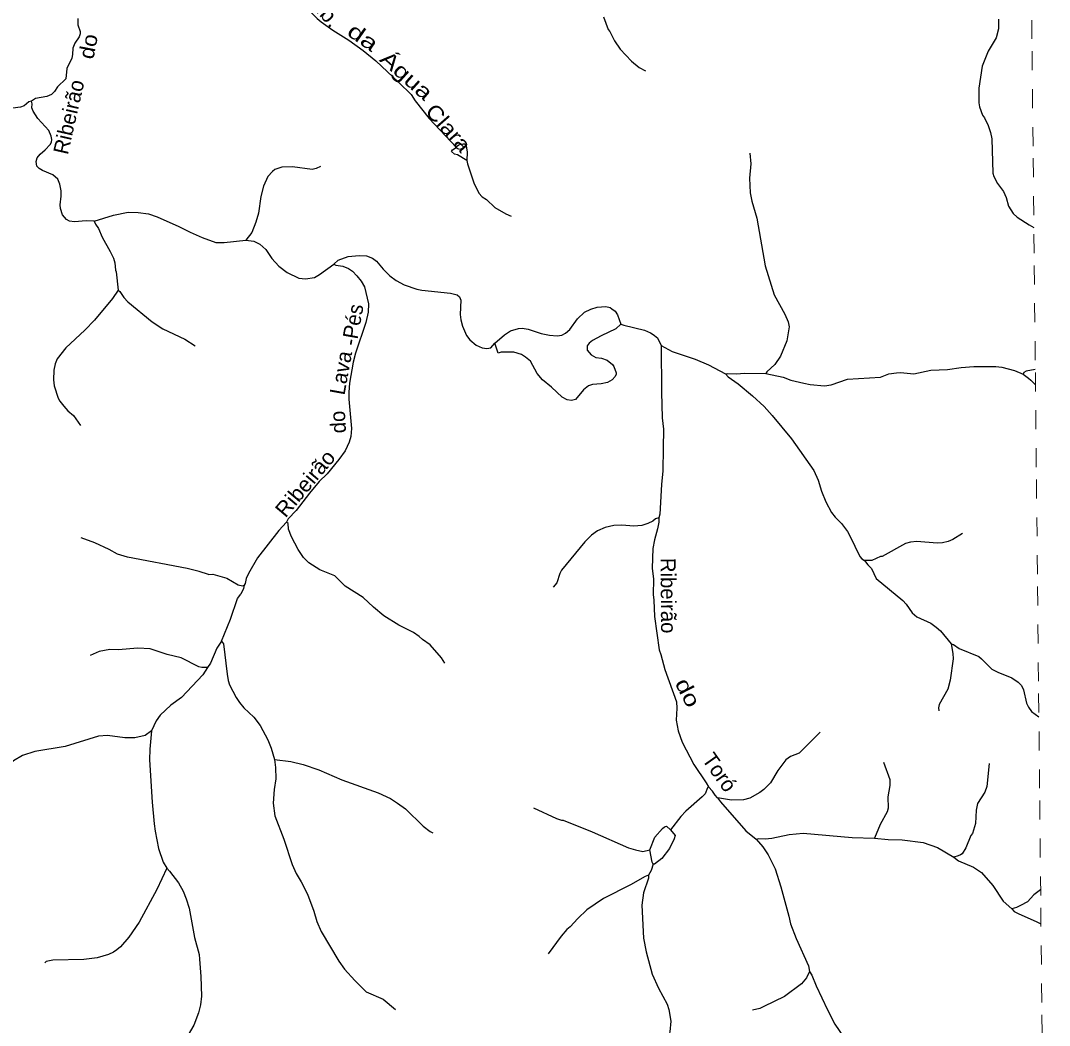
# Model space of a CAD drawing. Extents: x 320.3 to 346.3, y 7455.4 to 7483.3.
# Drawn here: x 340.83 to 346.26, y 7459.49 to 7464.8 of the extents above; entities that cross this region are included whole.
import ezdxf
from ezdxf.enums import TextEntityAlignment as Align

# ---------------------------------------------------------------- set-up
doc = ezdxf.new("R2010")
doc.units = 0
doc.header["$LTSCALE"] = 0.032
doc.linetypes.add('SHORT_DASHED', pattern=[2.7, 1.5, -1.2])
for name, color, linetype, lineweight in [('2', 7, 'Continuous', 25), ('53', 7, 'SHORT_DASHED', 13), ('7', 7, 'Continuous', 25)]:
    doc.layers.add(name, color=color, linetype=linetype, lineweight=lineweight)
doc.layers.add('61', color=7, linetype='Continuous')

msp = doc.modelspace()

# ---------------------------------------------------------------- linework, layer by layer
at = {"layer": '2'}
for points in [[(343.1018, 7464.1059), (343.1072, 7464.1137), (343.115, 7464.1191), (343.1228, 7464.125), (343.1261, 7464.1287), (343.1338, 7464.1355), (343.1411, 7464.1404), (343.1499, 7464.1439), (343.163, 7464.1468), (343.1723, 7464.1458), (343.1788, 7464.1352), (343.1846, 7464.1014), (343.1832, 7464.0579), (343.1329, 7464.0874), (343.1172, 7464.0923)], [(343.3306, 7463.0936), (343.3816, 7463.1375), (343.4129, 7463.1587), (343.4549, 7463.1712), (343.474, 7463.1733), (343.5071, 7463.1684), (343.5753, 7463.146), (343.6189, 7463.1359), (343.6591, 7463.1327), (343.6842, 7463.1369), (343.7044, 7463.1463), (343.7271, 7463.1666), (343.7679, 7463.2226), (343.8048, 7463.2585), (343.8381, 7463.2742), (343.8703, 7463.2839), (343.9173, 7463.2878), (343.9394, 7463.282), (343.9492, 7463.2757), (343.9651, 7463.2628), (343.9789, 7463.2429), (343.9963, 7463.1947), (343.9695, 7463.1691), (343.8912, 7463.1334), (343.8455, 7463.1077), (343.8284, 7463.094), (343.8179, 7463.0798), (343.8183, 7463.0567), (343.84, 7463.0322), (343.8643, 7463.0189), (343.8944, 7463.0141), (343.9241, 7463.0044), (343.9517, 7462.9817), (343.9589, 7462.9704), (343.9709, 7462.9383), (343.9713, 7462.9308), (343.9663, 7462.9183), (343.9506, 7462.9008), (343.9249, 7462.8872), (343.8927, 7462.8792), (343.8457, 7462.8752), (343.8254, 7462.8685), (343.7986, 7462.8483), (343.756, 7462.7972), (343.7349, 7462.7907), (343.7123, 7462.7949), (343.6868, 7462.8098), (343.6297, 7462.8623), (343.5825, 7462.9), (343.5539, 7462.9347), (343.5192, 7462.999), (343.4927, 7463.021), (343.471, 7463.0341), (343.4302, 7463.0463), (343.3638, 7463.0464), (343.3488, 7463.0422)], [(344.1497, 7460.4212), (344.1762, 7460.4867), (344.2159, 7460.5321), (344.226, 7460.5412), (344.2378, 7460.5449), (344.2574, 7460.526), (344.2824, 7460.4953), (344.2775, 7460.4781), (344.2536, 7460.4282), (344.2117, 7460.3739), (344.174, 7460.3443), (344.1671, 7460.3439), (344.1618, 7460.3553)]]:
    msp.add_lwpolyline(points, close=True, dxfattribs=at)
at = {"layer": '53'}
msp.add_lwpolyline([(346.259, 7455.6605), (346.2532, 7456.2254), (346.2474, 7456.7903), (346.2417, 7457.3553), (346.2359, 7457.9202), (346.2301, 7458.4852), (346.2243, 7459.0501), (346.2186, 7459.615), (346.2128, 7460.18), (346.207, 7460.7449), (346.2013, 7461.3098), (346.1955, 7461.8748), (346.1897, 7462.4397), (346.184, 7463.0046), (346.1782, 7463.5696), (346.1724, 7464.1345), (346.1667, 7464.6995), (346.1609, 7465.2644)], dxfattribs=at)
at = {"layer": '7'}
for points in [[(342.1435, 7465.3088), (342.1655, 7465.2439), (342.1816, 7465.1795), (342.1996, 7465.0843), (342.2112, 7465.0534), (342.3071, 7464.9054), (342.3489, 7464.8523), (342.3917, 7464.808), (342.4129, 7464.7906), (342.4746, 7464.7463), (342.56, 7464.693), (342.6361, 7464.6384), (342.7028, 7464.5832), (342.8244, 7464.47), (342.8888, 7464.4068), (342.9106, 7464.3735), (342.9844, 7464.2804), (343.1261, 7464.1287)], [(343.9046, 7464.8166), (343.929, 7464.7496), (343.9377, 7464.7391), (343.9622, 7464.6895), (343.9925, 7464.6457), (344.0519, 7464.5829), (344.093, 7464.5485), (344.1253, 7464.5318)], [(341.1286, 7464.8071), (341.1293, 7464.7745), (341.1402, 7464.7397), (341.1412, 7464.727), (341.1349, 7464.7106), (341.113, 7464.6779), (341.1015, 7464.6516), (341.1007, 7464.6173), (341.0961, 7464.5974), (341.0704, 7464.5437), (341.0658, 7464.4896), (341.022, 7464.4461), (341.0054, 7464.4217), (340.9892, 7464.4062), (340.9655, 7464.3955), (340.9047, 7464.385), (340.8846, 7464.3706)], [(345.99, 7464.8036), (345.9895, 7464.753), (345.9778, 7464.7061), (345.9359, 7464.6356), (345.9043, 7464.5559), (345.8857, 7464.44), (345.8864, 7464.3623), (345.8897, 7464.3417), (345.9051, 7464.2977), (345.917, 7464.2837), (345.9356, 7464.2431), (345.9481, 7464.2064), (345.9547, 7464.1732), (345.9595, 7463.9918), (345.965, 7463.974), (345.9847, 7463.9362), (346.0169, 7463.8939), (346.0301, 7463.8629), (346.0427, 7463.8177), (346.0682, 7463.7786), (346.0881, 7463.7583), (346.1518, 7463.7191), (346.1769, 7463.7037)], [(340.8846, 7464.3706), (340.87, 7464.3672), (340.8444, 7464.3473), (340.8255, 7464.3396), (340.7181, 7464.3255), (340.6758, 7464.3131), (340.6066, 7464.2651), (340.5819, 7464.2527), (340.4992, 7464.2423), (340.4007, 7464.2156), (340.3083, 7464.1825), (340.2685, 7464.1635)], [(341.2155, 7463.7378), (341.1718, 7463.7391), (341.1112, 7463.7337), (341.0842, 7463.7385), (341.069, 7463.7464), (341.0485, 7463.771), (341.0363, 7463.805), (341.0351, 7463.8243), (341.0414, 7463.8698), (341.0414, 7463.8986), (341.0337, 7463.9333), (341.0227, 7463.9595), (340.9974, 7463.983), (340.9425, 7464.0048), (340.925, 7464.0152), (340.9125, 7464.0281), (340.9081, 7464.0529), (340.9142, 7464.0716), (340.9303, 7464.0915), (340.9563, 7464.1138), (340.9825, 7464.1431), (340.9896, 7464.1552), (340.9907, 7464.1694), (340.9883, 7464.1862), (340.975, 7464.2163), (340.9168, 7464.2796), (340.8922, 7464.319), (340.8857, 7464.3359), (340.8873, 7464.3573), (340.8846, 7464.3706)], [(343.1832, 7464.0579), (343.1864, 7464.0403), (343.2204, 7463.9397), (343.2461, 7463.8853), (343.2634, 7463.8667), (343.2867, 7463.8518), (343.3298, 7463.8105), (343.3884, 7463.7766), (343.4173, 7463.7651)], [(344.6764, 7464.0966), (344.6824, 7464.0399), (344.6757, 7463.9644), (344.6781, 7463.888), (344.6873, 7463.8436), (344.7145, 7463.7535), (344.7583, 7463.503), (344.8051, 7463.3494), (344.8623, 7463.2475), (344.8794, 7463.2074), (344.8839, 7463.1804), (344.8732, 7463.1064), (344.8395, 7463.0257), (344.809, 7462.9809), (344.7669, 7462.9423), (344.7614, 7462.934)], [(342.4101, 7464.0258), (342.3871, 7464.0151), (342.3667, 7464.0105), (342.2628, 7464.0241), (342.2057, 7464.0237), (342.169, 7464.0106), (342.1558, 7464.0007), (342.1326, 7463.9736), (342.1096, 7463.922), (342.0944, 7463.8682), (342.0823, 7463.7798), (342.0692, 7463.7325), (342.0468, 7463.6786), (342.0149, 7463.6376)], [(341.2155, 7463.7378), (341.3167, 7463.7701), (341.3951, 7463.7847), (341.4476, 7463.7841), (341.5017, 7463.7766), (341.5467, 7463.7616), (341.6626, 7463.7104), (341.7221, 7463.6792), (341.7854, 7463.6517), (341.8572, 7463.6256), (341.9019, 7463.6245), (342.0149, 7463.6376)], [(341.2155, 7463.7378), (341.2226, 7463.7217), (341.2376, 7463.7001), (341.2566, 7463.6541), (341.3, 7463.5785), (341.3169, 7463.543), (341.3234, 7463.5187), (341.3271, 7463.4788), (341.3309, 7463.47), (341.3418, 7463.3741)], [(342.0149, 7463.6376), (342.0574, 7463.6321), (342.0897, 7463.6159), (342.1208, 7463.5877), (342.1526, 7463.5416), (342.1905, 7463.5008), (342.2343, 7463.4666), (342.2959, 7463.4378), (342.3306, 7463.4336), (342.3789, 7463.4407), (342.4048, 7463.456), (342.4806, 7463.5112)], [(342.4806, 7463.5112), (342.5027, 7463.5318), (342.5564, 7463.5512), (342.6139, 7463.5573), (342.6522, 7463.5558), (342.6845, 7463.5432), (342.7065, 7463.527), (342.7414, 7463.4851), (342.7767, 7463.4488), (342.8099, 7463.4244), (342.8526, 7463.4019), (342.9193, 7463.3785), (342.9447, 7463.3732), (343.0971, 7463.3586), (343.1314, 7463.3492), (343.1446, 7463.3385), (343.151, 7463.3204), (343.1479, 7463.2462), (343.1512, 7463.2173), (343.1592, 7463.184), (343.1811, 7463.134), (343.1991, 7463.1114), (343.2319, 7463.0844), (343.2634, 7463.0698), (343.2877, 7463.0656), (343.3092, 7463.0688), (343.3306, 7463.0936)], [(342.4806, 7463.5112), (342.4905, 7463.5066), (342.5274, 7463.5007), (342.558, 7463.4878), (342.5788, 7463.4734), (342.6018, 7463.4502), (342.6247, 7463.4216), (342.6419, 7463.3908), (342.6643, 7463.3012), (342.6615, 7463.2581), (342.6502, 7463.2031), (342.5955, 7463.042), (342.5826, 7462.9945), (342.5624, 7462.8831), (342.5589, 7462.8364), (342.56, 7462.7979), (342.574, 7462.6445), (342.5693, 7462.6008), (342.5615, 7462.5709), (342.5396, 7462.5254), (342.5065, 7462.4795), (342.4447, 7462.4048), (342.4037, 7462.3633), (342.3514, 7462.3026), (342.2817, 7462.2117), (342.2397, 7462.1679), (342.2302, 7462.15)], [(341.3418, 7463.3741), (341.3112, 7463.33), (341.2167, 7463.2159), (341.1649, 7463.1626), (341.0648, 7463.0701), (341.0198, 7463.0107), (341.0088, 7462.985), (341.001, 7462.952), (340.9994, 7462.9), (341.0036, 7462.8691), (341.0252, 7462.8033), (341.0336, 7462.7874), (341.055, 7462.7616), (341.0751, 7462.7365), (341.1056, 7462.7116), (341.1421, 7462.6597)], [(341.3418, 7463.3741), (341.3495, 7463.3676), (341.3709, 7463.3352), (341.3925, 7463.3119), (341.5205, 7463.2068), (341.5776, 7463.1705), (341.6931, 7463.1158), (341.7488, 7463.0796)], [(343.9963, 7463.1947), (344.0119, 7463.1883), (344.1217, 7463.1619), (344.1529, 7463.1489), (344.1672, 7463.1407), (344.1886, 7463.1215), (344.2093, 7463.0814)], [(344.2093, 7463.0814), (344.2098, 7462.8362), (344.2147, 7462.6998), (344.2206, 7462.641), (344.2194, 7462.5396), (344.2169, 7462.4202), (344.2098, 7462.349), (344.2014, 7462.1914), (344.1964, 7462.1715)], [(344.2093, 7463.0814), (344.2666, 7463.0496), (344.3878, 7463.0093), (344.4591, 7462.9792), (344.5484, 7462.9319)], [(344.7614, 7462.934), (344.8523, 7462.9141), (344.8927, 7462.8996), (344.9622, 7462.883), (344.996, 7462.8767), (345.0718, 7462.8696), (345.106, 7462.8749), (345.1923, 7462.9047), (345.367, 7462.9154), (345.4118, 7462.9322), (345.4514, 7462.9383), (345.4718, 7462.9391), (345.543, 7462.9323), (345.6322, 7462.9521), (345.72, 7462.9547), (345.793, 7462.9662), (345.8606, 7462.971), (345.9769, 7462.9702), (346.0071, 7462.9667), (346.0752, 7462.9499), (346.1195, 7462.9301)], [(344.5484, 7462.9319), (344.559, 7462.9339), (344.608, 7462.9319), (344.6475, 7462.9355), (344.7614, 7462.934)], [(344.5484, 7462.9319), (344.5629, 7462.9163), (344.6146, 7462.8799), (344.691, 7462.8166), (344.7524, 7462.7594), (344.7955, 7462.7116), (344.8967, 7462.589), (345.015, 7462.422), (345.0378, 7462.3707), (345.0554, 7462.3136), (345.0779, 7462.2575), (345.109, 7462.1997), (345.1272, 7462.1754), (345.1605, 7462.1416), (345.1919, 7462.0997), (345.2051, 7462.0779), (345.2576, 7461.9676), (345.2678, 7461.9558), (345.282, 7461.9477)], [(346.1845, 7462.9557), (346.1367, 7462.9459), (346.1245, 7462.9386), (346.1195, 7462.9301)], [(346.1195, 7462.9301), (346.1491, 7462.9087), (346.1603, 7462.898), (346.1854, 7462.8741)], [(344.1964, 7462.1715), (344.1793, 7462.1667), (344.1641, 7462.1549), (344.1392, 7462.1418), (344.1071, 7462.1325), (344.0653, 7462.1281), (344.0005, 7462.1343), (343.9597, 7462.1325), (343.9126, 7462.1221), (343.8725, 7462.104), (343.8409, 7462.0802), (343.8066, 7462.0462), (343.682, 7461.896), (343.6729, 7461.8787), (343.6581, 7461.8292), (343.6378, 7461.8061)], [(344.1964, 7462.1715), (344.1962, 7462.1497), (344.1896, 7462.1136), (344.1729, 7462.0568), (344.1647, 7462.0103), (344.1616, 7461.9061), (344.1678, 7461.8485), (344.1663, 7461.7677), (344.1707, 7461.7375), (344.1744, 7461.6509), (344.1986, 7461.476), (344.2076, 7461.4515), (344.2279, 7461.3717), (344.2902, 7461.2005), (344.2917, 7461.1688), (344.2878, 7461.1048), (344.2981, 7461.049), (344.3189, 7460.9883), (344.3811, 7460.8709), (344.4473, 7460.7736), (344.4584, 7460.753)], [(342.2302, 7462.15), (342.1897, 7462.1054), (342.0778, 7461.9606), (342.029, 7461.8789), (342.0175, 7461.8527), (342.013, 7461.8267), (342.0076, 7461.8166)], [(343.0666, 7461.4062), (343.0485, 7461.4343), (342.9898, 7461.5017), (342.9484, 7461.5303), (342.9303, 7461.5468), (342.9014, 7461.5672), (342.8237, 7461.6058), (342.7437, 7461.6544), (342.689, 7461.7003), (342.6359, 7461.7511), (342.5399, 7461.8122), (342.4864, 7461.8658), (342.4069, 7461.8972), (342.3476, 7461.9349), (342.3201, 7461.9624), (342.2924, 7462.0057), (342.2561, 7462.0729), (342.2416, 7462.1118), (342.2384, 7462.1426), (342.2302, 7462.15)], [(341.8182, 7461.8733), (341.7695, 7461.8897), (341.7067, 7461.9048), (341.3913, 7461.9643), (341.3389, 7461.9798), (341.2948, 7462.0048), (341.2192, 7462.0412), (341.147, 7462.0667)], [(345.8003, 7462.0893), (345.7496, 7462.0587), (345.724, 7462.0476), (345.6952, 7462.0408), (345.6663, 7462.0394), (345.5597, 7462.0474), (345.526, 7462.0442), (345.4996, 7462.0375), (345.3763, 7461.9689), (345.3666, 7461.9677), (345.3208, 7461.9475), (345.282, 7461.9477)], [(345.282, 7461.9477), (345.2997, 7461.9238), (345.3196, 7461.9051), (345.3445, 7461.8515), (345.4848, 7461.7361), (345.5025, 7461.7171), (345.535, 7461.6713), (345.5594, 7461.6501), (345.6321, 7461.6168), (345.6615, 7461.5961), (345.683, 7461.5753), (345.7408, 7461.5076)], [(341.8182, 7461.8733), (341.8407, 7461.8752), (341.9147, 7461.8543), (341.9752, 7461.819), (341.9979, 7461.8142), (342.0076, 7461.8166)], [(342.0076, 7461.8166), (342.0035, 7461.8003), (341.9888, 7461.7691)], [(341.8879, 7461.5223), (341.9356, 7461.6371), (341.9724, 7461.7475), (341.9888, 7461.7691)], [(341.8879, 7461.5223), (341.863, 7461.484), (341.829, 7461.4052), (341.8138, 7461.3821)], [(341.8879, 7461.5223), (341.8984, 7461.5081), (341.9168, 7461.3482), (341.9226, 7461.3136), (341.9299, 7461.2913), (341.9638, 7461.2244), (341.9816, 7461.1981), (342.0054, 7461.1705), (342.0576, 7461.1198), (342.0912, 7461.0765), (342.1327, 7461.0009), (342.1494, 7460.9572), (342.1673, 7460.8969)], [(345.7408, 7461.5076), (345.7498, 7461.456), (345.7512, 7461.4276), (345.7346, 7461.316), (345.7219, 7461.2682), (345.677, 7461.1865), (345.6735, 7461.17), (345.6756, 7461.1544)], [(345.7408, 7461.5076), (345.7525, 7461.5034), (345.7822, 7461.4823), (345.8854, 7461.4398), (345.9005, 7461.4287), (345.955, 7461.3742), (345.9873, 7461.3578), (346.0602, 7461.3283), (346.0932, 7461.3048), (346.1116, 7461.2871), (346.1226, 7461.264), (346.1375, 7461.1951), (346.1486, 7461.1728), (346.1643, 7461.1504), (346.2032, 7461.123)], [(341.8138, 7461.3821), (341.7842, 7461.3826), (341.7682, 7461.3866), (341.6748, 7461.433), (341.6009, 7461.4518), (341.5104, 7461.4814), (341.4448, 7461.484), (341.3419, 7461.476), (341.2967, 7461.4771), (341.2421, 7461.4662), (341.1936, 7461.4465)], [(341.8138, 7461.3821), (341.7888, 7461.3433), (341.6762, 7461.2241), (341.6205, 7461.1833), (341.5628, 7461.1305), (341.5419, 7461.1005), (341.5179, 7461.048)], [(341.5179, 7461.048), (341.4833, 7461.024), (341.4297, 7461.0119), (341.3766, 7461.0117), (341.2852, 7461.0238), (341.2372, 7461.0209), (341.0621, 7460.9662), (340.9007, 7460.9393), (340.8364, 7460.9173), (340.7884, 7460.8897), (340.7424, 7460.8496), (340.6198, 7460.6949), (340.5795, 7460.6486), (340.5584, 7460.6174)], [(341.5179, 7461.048), (341.5079, 7460.9518), (341.5074, 7460.8956), (341.5205, 7460.6724), (341.531, 7460.5584), (341.5361, 7460.5189), (341.555, 7460.4273), (341.5793, 7460.3555), (341.5979, 7460.3229)], [(345.0489, 7461.041), (344.9368, 7460.931), (344.8914, 7460.9123), (344.8673, 7460.8951), (344.8253, 7460.8382), (344.7855, 7460.7745), (344.7508, 7460.7383), (344.7294, 7460.7226), (344.6776, 7460.6933), (344.643, 7460.6834), (344.581, 7460.6825), (344.507, 7460.6956)], [(342.1673, 7460.8969), (342.1726, 7460.8545), (342.1742, 7460.7952), (342.1648, 7460.7392), (342.16, 7460.6672), (342.1689, 7460.6004), (342.2164, 7460.4773), (342.2596, 7460.3432), (342.2817, 7460.2946), (342.3083, 7460.251), (342.3408, 7460.186), (342.3752, 7460.0973), (342.3911, 7460.0425), (342.4128, 7459.9897), (342.5062, 7459.8327), (342.5367, 7459.7912), (342.5913, 7459.7308), (342.6517, 7459.6708), (342.7411, 7459.6328), (342.8059, 7459.5783)], [(342.1673, 7460.8969), (342.2525, 7460.8858), (342.3181, 7460.871), (342.4006, 7460.842), (342.5231, 7460.7905), (342.7143, 7460.721), (342.7801, 7460.6904), (342.8169, 7460.6668), (342.8581, 7460.6359), (342.9514, 7460.5449), (342.9882, 7460.5176), (343.0038, 7460.51)], [(345.382, 7460.8833), (345.4157, 7460.7908), (345.4163, 7460.7605), (345.4066, 7460.7006), (345.4068, 7460.641), (345.4019, 7460.6204), (345.3645, 7460.5532), (345.3359, 7460.4823)], [(345.9411, 7460.8752), (345.9291, 7460.7546), (345.9174, 7460.7238), (345.8798, 7460.6644), (345.8718, 7460.6291), (345.8678, 7460.5588), (345.8536, 7460.5062), (345.8444, 7460.4961), (345.8168, 7460.4315), (345.7977, 7460.3998), (345.7889, 7460.3946), (345.7779, 7460.3887), (345.7538, 7460.3823)], [(344.4584, 7460.753), (344.4528, 7460.7481), (344.4404, 7460.7165), (344.4261, 7460.6995), (344.3393, 7460.6241), (344.3126, 7460.5955), (344.2574, 7460.526)], [(344.507, 7460.6956), (344.4932, 7460.7081), (344.4799, 7460.7293), (344.4584, 7460.753)], [(344.507, 7460.6956), (344.5224, 7460.6733), (344.6566, 7460.52), (344.7101, 7460.4775)], [(343.5348, 7460.6419), (343.6556, 7460.5853), (343.6817, 7460.5764), (343.6912, 7460.5761), (343.8445, 7460.5161), (344.0358, 7460.4303), (344.0731, 7460.4202), (344.1122, 7460.4115), (344.1497, 7460.4212)], [(344.7101, 7460.4775), (344.7249, 7460.4805), (344.7582, 7460.4785), (344.7935, 7460.4817), (344.8845, 7460.5021), (344.9595, 7460.5078), (345.217, 7460.4849), (345.3359, 7460.4823)], [(344.7101, 7460.4775), (344.7453, 7460.4366), (344.7735, 7460.3941), (344.8112, 7460.3197), (344.8403, 7460.2256), (344.8837, 7460.0698), (344.8923, 7460.0293), (344.9215, 7459.9526), (344.9864, 7459.8085), (344.9923, 7459.7782)], [(345.3359, 7460.4823), (345.4073, 7460.4745), (345.4815, 7460.4738), (345.5925, 7460.4594), (345.6686, 7460.4329), (345.7538, 7460.3823)], [(345.7538, 7460.3823), (345.7786, 7460.3631), (345.8574, 7460.3286), (345.9002, 7460.3), (345.9603, 7460.2324), (346.0156, 7460.1496), (346.0603, 7460.1095)], [(341.5979, 7460.3229), (341.546, 7460.2113), (341.4522, 7460.0395), (341.3971, 7459.9595), (341.3544, 7459.909), (341.3348, 7459.8924), (341.3167, 7459.8797), (341.2909, 7459.8674), (341.2307, 7459.8507), (341.1597, 7459.8414), (340.9965, 7459.8386), (340.9606, 7459.8307), (340.9539, 7459.8245)], [(341.5979, 7460.3229), (341.6125, 7460.3084), (341.6599, 7460.2464), (341.685, 7460.2016), (341.7014, 7460.162), (341.7173, 7460.112), (341.7446, 7459.9582), (341.7685, 7459.8683), (341.7718, 7459.8437), (341.7783, 7459.7523), (341.7808, 7459.6479), (341.7772, 7459.6028), (341.7654, 7459.5601), (341.7406, 7459.4952), (341.7116, 7459.4438), (341.689, 7459.4141)], [(344.1671, 7460.3439), (344.1557, 7460.3113), (344.1423, 7460.2867)], [(344.1423, 7460.2867), (344.1243, 7460.2798), (344.0472, 7460.2353), (343.9048, 7460.1633), (343.8163, 7460.1032), (343.769, 7460.0583), (343.7284, 7460.0136), (343.7109, 7460.0008), (343.6811, 7459.9649), (343.6128, 7459.8712)], [(344.1423, 7460.2867), (344.1411, 7460.2706), (344.1148, 7460.1929), (344.1072, 7460.1278), (344.1152, 7459.9538), (344.1294, 7459.8816), (344.1605, 7459.765), (344.1941, 7459.691), (344.2399, 7459.6051), (344.2496, 7459.5775), (344.26, 7459.516), (344.2544, 7459.4595), (344.2421, 7459.4102), (344.228, 7459.3712), (344.1848, 7459.3015), (344.1127, 7459.2211), (344.0475, 7459.169), (343.9619, 7459.0784), (343.9242, 7459.0482)], [(346.2125, 7460.2098), (346.177, 7460.1823), (346.1434, 7460.146), (346.1063, 7460.1263), (346.085, 7460.1161), (346.0603, 7460.1095)], [(346.0603, 7460.1095), (346.0725, 7460.0956), (346.0981, 7460.0821), (346.1893, 7460.0414), (346.2144, 7460.0302)], [(344.9923, 7459.7782), (344.9758, 7459.7447), (344.9498, 7459.7128), (344.8595, 7459.6459), (344.7516, 7459.5928), (344.73, 7459.5837), (344.6917, 7459.5735)], [(344.9923, 7459.7782), (345.0049, 7459.7581), (345.0271, 7459.7022), (345.0867, 7459.5761), (345.1261, 7459.5006), (345.1938, 7459.3999), (345.2198, 7459.3685), (345.2473, 7459.3226), (345.2804, 7459.243), (345.2994, 7459.1574), (345.3115, 7459.1324)]]:
    msp.add_lwpolyline(points, dxfattribs=at)

# ---------------------------------------------------------------- texts
at = {"layer": '61'}
for s, rotation, width, p in [('Rib.', 311.451, 1.1, (342.3959, 7464.831)), ('da', 325.176, 1.4, (342.6117, 7464.6764)), ('do', 78.826, 1.1, (341.2228, 7464.6526)), ('Água', 318.158, 1.3, (342.838, 7464.4775)), ('Clara', 311.216, 1.15, (343.0552, 7464.2037)), ('Ribeirão', 49.842, 1.05, (342.3597, 7462.3284)), ('do', 296.973, 1.3, (344.3142, 7461.2319))]:
    msp.add_text(s, height=0.08, rotation=rotation, dxfattribs=dict(at, width=width)).set_placement(p, align=Align.CENTER)
for s, rotation, p in [('Ribeirão', 77.182, (341.1198, 7464.2792)), ('-Pés', 79.777, (342.6185, 7463.1845)), ('Lava', 79.777, (342.557, 7462.9306)), ('do', 93.158, (342.5416, 7462.6798)), ('Ribeirão', 270.459, (344.2069, 7461.7615)), ('Toró', 305.134, (344.4846, 7460.8068))]:
    msp.add_text(s, height=0.08, rotation=rotation, dxfattribs=at).set_placement(p, align=Align.CENTER)

doc.saveas('drawing.dxf')
